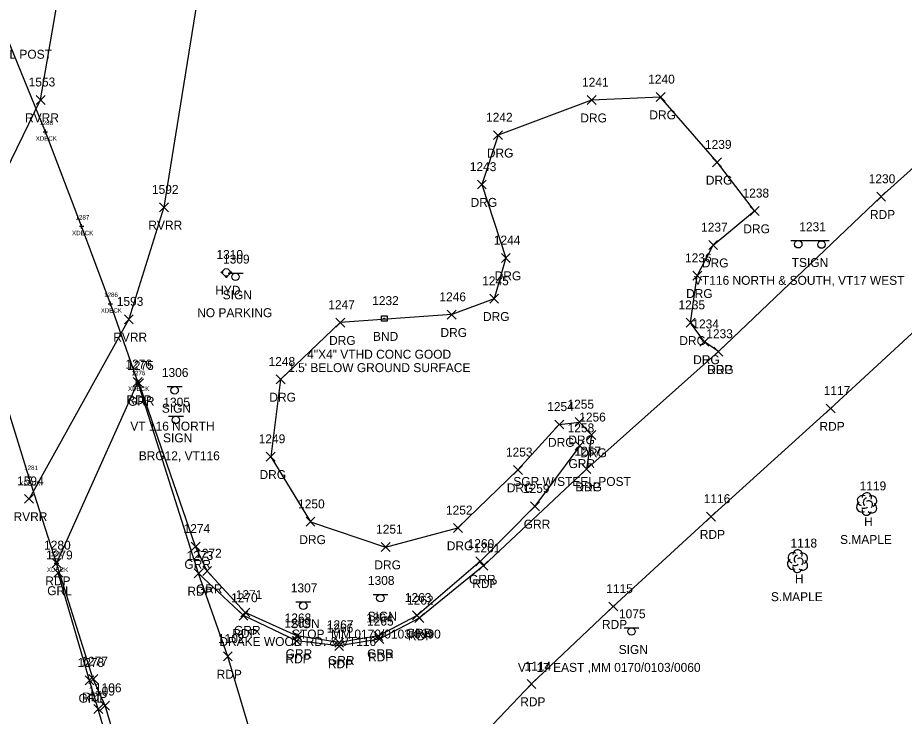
# Model space of a CAD drawing. Extents: x 1496556 to 1498241, y 599216 to 604470.
# Drawn here: x 1497204.8 to 1497403.3, y 603012.5 to 603168.8 of the extents above; entities that cross this region are included whole.
import ezdxf

# ---------------------------------------------------------------- set-up
doc = ezdxf.new("R2010")
doc.units = 0
for name, color, linetype in [('B_A', 7, 'Continuous'), ('B_I', 7, 'Continuous'), ('B_TIC', 7, 'Continuous'), ('BELB', 7, 'Continuous'), ('L_A', 7, 'Continuous'), ('L_C', 7, 'Continuous'), ('L_I', 7, 'Continuous'), ('L_TIC', 7, 'Continuous'), ('LAWE', 7, 'Continuous'), ('Level 18', 7, 'Continuous'), ('LTD', 7, 'Continuous'), ('M_A', 7, 'Continuous'), ('M_C', 7, 'Continuous'), ('M_I', 7, 'Continuous'), ('P_A', 7, 'Continuous'), ('P_I', 7, 'Continuous'), ('P_TIC', 7, 'Continuous'), ('PET', 7, 'Continuous'), ('R_A', 7, 'Continuous'), ('R_C', 7, 'Continuous'), ('R_I', 7, 'Continuous'), ('R_TIC', 7, 'Continuous'), ('RDG', 7, 'Continuous'), ('RGR', 7, 'Continuous'), ('S_A', 7, 'Continuous'), ('S_C', 7, 'Continuous'), ('S_I', 7, 'Continuous'), ('SSGN', 7, 'Continuous'), ('U_A', 7, 'Continuous'), ('U_I', 7, 'Continuous'), ('UWFH', 7, 'Continuous')]:
    doc.layers.add(name, color=color, linetype=linetype)

msp = doc.modelspace()

# ---------------------------------------------------------------- linework, layer by layer
at = {"layer": 'B_TIC'}
for p, q in [((1497211.03, 603143.32), (1497211.1, 603143.32)), ((1497219.15, 603122.16), (1497219.22, 603122.16)), ((1497225.58, 603104.83), (1497225.65, 603104.83)), ((1497231.71, 603087.32), (1497231.78, 603087.32)), ((1497207.36, 603066.11), (1497207.44, 603066.11)), ((1497213.54, 603046.79), (1497213.61, 603046.79))]:
    msp.add_line(p, q, dxfattribs=at)
for points in [[(1497211.03, 603142.82), (1497211.03, 603143.82)], [(1497210.53, 603143.32), (1497211.53, 603143.32)], [(1497218.64, 603122.16), (1497219.64, 603122.16)], [(1497219.14, 603121.66), (1497219.14, 603122.66)], [(1497225.08, 603104.83), (1497226.08, 603104.83)], [(1497225.58, 603104.33), (1497225.58, 603105.33)], [(1497231.2, 603087.32), (1497232.2, 603087.32)], [(1497231.7, 603086.82), (1497231.7, 603087.82)], [(1497207.36, 603065.61), (1497207.36, 603066.61)], [(1497206.86, 603066.11), (1497207.86, 603066.11)], [(1497213.03, 603046.79), (1497214.03, 603046.79)], [(1497213.53, 603046.29), (1497213.53, 603047.29)]]:
    msp.add_lwpolyline(points, dxfattribs=at)
at = {"layer": 'BELB'}
for points in [[(1497213.53, 603046.79), (1497207.36, 603066.11), (1497200.63, 603087.66), (1497189.92, 603115.25), (1497185.37, 603127.09), (1497183.49, 603131.83), (1497200.78, 603168.36)], [(1497231.7, 603087.32), (1497225.58, 603104.83), (1497219.14, 603122.16), (1497211.03, 603143.32), (1497200.78, 603168.36)]]:
    msp.add_lwpolyline(points, dxfattribs=at)
at = {"layer": 'L_TIC'}
for points in [[(1497208.98, 603149.46), (1497210.98, 603151.46)], [(1497210.98, 603149.46), (1497208.98, 603151.46)], [(1497236.58, 603125.42), (1497238.58, 603127.42)], [(1497238.58, 603125.42), (1497236.58, 603127.42)], [(1497228.71, 603100.35), (1497230.71, 603102.35)], [(1497230.71, 603100.35), (1497228.71, 603102.35)], [(1497206.4, 603060.16), (1497208.4, 603062.16)], [(1497208.4, 603060.16), (1497206.4, 603062.16)]]:
    msp.add_lwpolyline(points, dxfattribs=at)
at = {"layer": 'LAWE'}
for points in [[(1497189.81, 603091.49), (1497191.67, 603112.98), (1497209.98, 603150.46), (1497214.03, 603174.34), (1497209.01, 603206.37), (1497211.24, 603222.01), (1497227.45, 603268.03), (1497246.38, 603332.34), (1497269.89, 603360.04), (1497296.95, 603397.6), (1497313.57, 603422.44), (1497323.64, 603438.94), (1497334.8, 603445.38), (1497344.77, 603450.19), (1497370.1, 603467.8), (1497419.49, 603471.31), (1497456.04, 603468.84), (1497488.04, 603460.85), (1497518.38, 603461.84), (1497564.45, 603467.31)], [(1497257.29, 603233.96), (1497249.44, 603200.12), (1497237.58, 603126.42), (1497229.71, 603101.35), (1497207.4, 603061.16)]]:
    msp.add_lwpolyline(points, dxfattribs=at)
at = {"layer": 'Level 18'}
msp.add_lwpolyline([(1497286.25, 603102.14), (1497287.5, 603102.14), (1497287.5, 603100.89), (1497286.25, 603100.89)], close=True, dxfattribs=at)
msp.add_circle((1497286.87, 603101.52), 0.0833, dxfattribs=at)
at = {"layer": 'LTD'}
for p, q in [((1497394.85, 603060.05), (1497394.85, 603060.05)), ((1497394.85, 603060.05), (1497394.85, 603060.05)), ((1497379.36, 603047.25), (1497379.36, 603047.25)), ((1497379.36, 603047.25), (1497379.36, 603047.25))]:
    msp.add_line(p, q, dxfattribs=at)
for centre in [(1497394.89, 603061.48), (1497379.41, 603048.68)]:
    msp.add_arc(centre, 1.05, 335.5272, 180.9563, dxfattribs=at)
for centre, major_axis, ratio, start_param, end_param in [((1497394.05, 603060.72), (1.21, -0.51), 0.895232, 1.570796, 4.712389), ((1497394.64, 603060.51), (-0.208, -0.792), 0.645439, 3.141593, 6.283185), ((1497395.35, 603059.88), (-0.5, 0.667), 0.989748, 3.141593, 6.283185), ((1497395.89, 603060.63), (-1.14, -0.48), 0.949671, 1.570796, 4.712389), ((1497393.76, 603059.34), (0.58, -1.04), 0.959034, 3.141593, 6.283185), ((1497394.85, 603058.55), (0.26, 1.06), 0.942809, 1.570796, 4.712389), ((1497394.39, 603059.3), (-0.625, -0.083), 0.423636, 0, 3.141593), ((1497395.85, 603059.22), (-1.09, 0.79), 0.841452, 1.570796, 4.712389), ((1497378.57, 603047.91), (1.21, -0.51), 0.895232, 1.570796, 4.712389), ((1497379.16, 603047.71), (-0.208, -0.792), 0.645439, 3.141593, 6.283185), ((1497380.41, 603047.83), (-1.14, -0.48), 0.949671, 1.570796, 4.712389), ((1497378.28, 603046.54), (0.58, -1.04), 0.959034, 3.141593, 6.283185), ((1497379.86, 603047.08), (-0.5, 0.667), 0.989748, 3.141593, 6.283185), ((1497380.36, 603046.41), (-1.09, 0.79), 0.841452, 1.570796, 4.712389), ((1497379.36, 603045.75), (0.26, 1.06), 0.942809, 1.570796, 4.712389), ((1497378.91, 603046.5), (-0.625, -0.083), 0.423636, 0, 3.141593)]:
    msp.add_ellipse(centre, major_axis=major_axis, ratio=ratio, start_param=start_param, end_param=end_param, dxfattribs=at)
at = {"layer": 'P_TIC'}
for points in [[(1497397.1, 603127.8), (1497399.1, 603129.8)], [(1497399.1, 603127.8), (1497397.1, 603129.8)], [(1497360.66, 603093.11), (1497362.66, 603095.11)], [(1497362.66, 603093.11), (1497360.66, 603095.11)], [(1497230.7, 603086.32), (1497232.7, 603088.32)], [(1497232.7, 603086.32), (1497230.7, 603088.32)], [(1497385.8, 603080.38), (1497387.8, 603082.38)], [(1497387.8, 603080.38), (1497385.8, 603082.38)], [(1497331.15, 603066.83), (1497333.15, 603068.83)], [(1497333.15, 603066.83), (1497331.15, 603068.83)], [(1497359.02, 603056.19), (1497361.02, 603058.19)], [(1497361.02, 603056.19), (1497359.02, 603058.19)], [(1497212.53, 603045.79), (1497214.53, 603047.79)], [(1497214.53, 603045.79), (1497212.53, 603047.79)], [(1497212.53, 603045.79), (1497214.53, 603047.79)], [(1497214.53, 603045.79), (1497212.53, 603047.79)], [(1497308.09, 603045.17), (1497310.09, 603047.17)], [(1497310.09, 603045.17), (1497308.09, 603047.17)], [(1497244.34, 603043.47), (1497246.34, 603045.47)], [(1497246.34, 603043.47), (1497244.34, 603045.47)], [(1497244.34, 603043.47), (1497246.34, 603045.47)], [(1497246.34, 603043.47), (1497244.34, 603045.47)], [(1497337.13, 603036.05), (1497339.13, 603038.05)], [(1497339.13, 603036.05), (1497337.13, 603038.05)], [(1497254.38, 603034.01), (1497256.38, 603036.01)], [(1497256.38, 603034.01), (1497254.38, 603036.01)], [(1497293.72, 603033.46), (1497295.72, 603035.46)], [(1497295.72, 603033.46), (1497293.72, 603035.46)], [(1497284.78, 603028.77), (1497286.78, 603030.77)], [(1497286.78, 603028.77), (1497284.78, 603030.77)], [(1497266.28, 603028.35), (1497268.28, 603030.35)], [(1497268.28, 603028.35), (1497266.28, 603030.35)], [(1497275.79, 603027.23), (1497277.79, 603029.23)], [(1497277.79, 603027.23), (1497275.79, 603029.23)], [(1497250.88, 603024.88), (1497252.88, 603026.88)], [(1497252.88, 603024.88), (1497250.88, 603026.88)], [(1497220.77, 603019.8), (1497222.77, 603021.8)], [(1497222.77, 603019.8), (1497220.77, 603021.8)], [(1497318.84, 603018.72), (1497320.84, 603020.72)], [(1497320.84, 603018.72), (1497318.84, 603020.72)], [(1497223.39, 603013.86), (1497225.39, 603015.86)], [(1497225.39, 603013.86), (1497223.39, 603015.86)]]:
    msp.add_lwpolyline(points, dxfattribs=at)
at = {"layer": 'PET'}
for points in [[(1497580.33, 603293.36), (1497544.07, 603260.5), (1497503.96, 603223.83), (1497469.44, 603192.83), (1497432.27, 603159.48), (1497398.1, 603128.8), (1497361.66, 603094.11), (1497332.15, 603067.83), (1497309.09, 603046.17), (1497294.72, 603034.46), (1497285.78, 603029.77), (1497276.79, 603028.23), (1497267.28, 603029.35), (1497255.38, 603035.01), (1497245.34, 603044.47)], [(1497277.08, 602932.51), (1497278.76, 602955.27), (1497283.83, 602972.38), (1497292.85, 602989.5), (1497302.51, 603001.53), (1497319.84, 603019.72), (1497338.13, 603037.05), (1497360.02, 603057.19), (1497386.8, 603081.38), (1497411.61, 603104.29), (1497436.99, 603126.72), (1497459.34, 603147.15), (1497493.2, 603178.11), (1497522.29, 603204.31), (1497552.95, 603231.97)], [(1497283.12, 602906.81), (1497277.08, 602932.51), (1497269.71, 602963.41), (1497262.37, 602990.53), (1497251.88, 603025.88), (1497245.34, 603044.47), (1497231.7, 603087.32), (1497213.53, 603046.79)], [(1497255.35, 601840.33), (1497260.72, 601945.51), (1497260.6, 601945.5), (1497265.21, 602060.91), (1497267.76, 602124.12), (1497271.3, 602209.29), (1497274.95, 602307.82), (1497276.81, 602364.31), (1497278.84, 602406.87), (1497280.41, 602449.54), (1497282.45, 602505.14), (1497283.29, 602549.03), (1497283.31, 602599.78), (1497282.4, 602667.07), (1497280.87, 602701.36), (1497277.35, 602744.02), (1497266.99, 602833.93), (1497261.25, 602868.44), (1497249.2, 602924.4), (1497241.75, 602954.09), (1497234.18, 602981.9), (1497224.39, 603014.86), (1497221.77, 603020.8), (1497213.53, 603046.79)]]:
    msp.add_lwpolyline(points, dxfattribs=at)
at = {"layer": 'R_TIC'}
for points in [[(1497347.74, 603150.1), (1497349.74, 603152.1)], [(1497349.74, 603150.1), (1497347.74, 603152.1)], [(1497332.28, 603149.41), (1497334.28, 603151.41)], [(1497334.28, 603149.41), (1497332.28, 603151.41)], [(1497311.37, 603141.56), (1497313.37, 603143.56)], [(1497313.37, 603141.56), (1497311.37, 603143.56)], [(1497360.37, 603135.49), (1497362.37, 603137.49)], [(1497362.37, 603135.49), (1497360.37, 603137.49)], [(1497307.72, 603130.51), (1497309.72, 603132.51)], [(1497309.72, 603130.51), (1497307.72, 603132.51)], [(1497368.77, 603124.6), (1497370.77, 603126.6)], [(1497370.77, 603124.6), (1497368.77, 603126.6)], [(1497359.5, 603116.96), (1497361.5, 603118.96)], [(1497361.5, 603116.96), (1497359.5, 603118.96)], [(1497313.1, 603114.07), (1497315.1, 603116.07)], [(1497315.1, 603114.07), (1497313.1, 603116.07)], [(1497355.95, 603110.1), (1497357.95, 603112.1)], [(1497357.95, 603110.1), (1497355.95, 603112.1)], [(1497310.49, 603104.96), (1497312.49, 603106.96)], [(1497312.49, 603104.96), (1497310.49, 603106.96)], [(1497300.98, 603101.38), (1497302.98, 603103.38)], [(1497302.98, 603101.38), (1497300.98, 603103.38)], [(1497276.05, 603099.61), (1497278.05, 603101.61)], [(1497278.05, 603099.61), (1497276.05, 603101.61)], [(1497354.44, 603099.57), (1497356.44, 603101.57)], [(1497356.44, 603099.57), (1497354.44, 603101.57)], [(1497357.54, 603095.3), (1497359.54, 603097.3)], [(1497359.54, 603095.3), (1497357.54, 603097.3)], [(1497360.66, 603093.11), (1497362.66, 603095.11)], [(1497362.66, 603093.11), (1497360.66, 603095.11)], [(1497262.68, 603086.9), (1497264.68, 603088.9)], [(1497264.68, 603086.9), (1497262.68, 603088.9)], [(1497231.03, 603085.99), (1497233.03, 603087.99)], [(1497233.03, 603085.99), (1497231.03, 603087.99)], [(1497325.05, 603076.8), (1497327.05, 603078.8)], [(1497327.05, 603076.8), (1497325.05, 603078.8)], [(1497329.58, 603077.33), (1497331.58, 603079.33)], [(1497331.58, 603077.33), (1497329.58, 603079.33)], [(1497332.27, 603074.46), (1497334.27, 603076.46)], [(1497334.27, 603074.46), (1497332.27, 603076.46)], [(1497329.63, 603072.04), (1497331.63, 603074.04)], [(1497331.63, 603072.04), (1497329.63, 603074.04)], [(1497260.49, 603069.59), (1497262.49, 603071.59)], [(1497262.49, 603069.59), (1497260.49, 603071.59)], [(1497315.81, 603066.62), (1497317.81, 603068.62)], [(1497317.81, 603066.62), (1497315.81, 603068.62)], [(1497331.15, 603066.83), (1497333.15, 603068.83)], [(1497333.15, 603066.83), (1497331.15, 603068.83)], [(1497319.62, 603058.49), (1497321.62, 603060.49)], [(1497321.62, 603058.49), (1497319.62, 603060.49)], [(1497269.38, 603055.02), (1497271.38, 603057.02)], [(1497271.38, 603055.02), (1497269.38, 603057.02)], [(1497302.39, 603053.64), (1497304.39, 603055.64)], [(1497304.39, 603053.64), (1497302.39, 603055.64)], [(1497243.66, 603049.49), (1497245.66, 603051.49)], [(1497245.66, 603049.49), (1497243.66, 603051.49)], [(1497286.19, 603049.37), (1497288.19, 603051.37)], [(1497288.19, 603049.37), (1497286.19, 603051.37)], [(1497307.38, 603046.14), (1497309.38, 603048.14)], [(1497309.38, 603046.14), (1497307.38, 603048.14)], [(1497212.91, 603043.59), (1497214.91, 603045.59)], [(1497214.91, 603043.59), (1497212.91, 603045.59)], [(1497246.25, 603043.98), (1497248.25, 603045.98)], [(1497248.25, 603043.98), (1497246.25, 603045.98)], [(1497254.77, 603034.71), (1497256.77, 603036.71)], [(1497256.77, 603034.71), (1497254.77, 603036.71)], [(1497293.23, 603034.06), (1497295.23, 603036.06)], [(1497295.23, 603034.06), (1497293.23, 603036.06)], [(1497266.33, 603029.49), (1497268.33, 603031.49)], [(1497268.33, 603029.49), (1497266.33, 603031.49)], [(1497284.58, 603029.48), (1497286.58, 603031.48)], [(1497286.58, 603029.48), (1497284.58, 603031.48)], [(1497275.79, 603027.97), (1497277.79, 603029.97)], [(1497277.79, 603027.97), (1497275.79, 603029.97)], [(1497219.92, 603019.52), (1497221.92, 603021.52)], [(1497221.92, 603019.52), (1497219.92, 603021.52)], [(1497221.87, 603013.11), (1497223.87, 603015.11)], [(1497223.87, 603013.11), (1497221.87, 603015.11)]]:
    msp.add_lwpolyline(points, dxfattribs=at)
at = {"layer": 'RDG'}
msp.add_lwpolyline([(1497361.66, 603094.11), (1497358.54, 603096.3), (1497355.44, 603100.57), (1497356.95, 603111.1), (1497360.5, 603117.96), (1497369.77, 603125.6), (1497361.37, 603136.49), (1497348.74, 603151.1), (1497333.28, 603150.41), (1497312.37, 603142.56), (1497308.72, 603131.51), (1497314.1, 603115.07), (1497311.49, 603105.96), (1497301.98, 603102.38), (1497277.05, 603100.61), (1497263.68, 603087.9), (1497261.49, 603070.59), (1497270.38, 603056.02), (1497287.19, 603050.37), (1497303.39, 603054.64), (1497316.81, 603067.62), (1497326.05, 603077.8), (1497330.58, 603078.33), (1497333.27, 603075.46), (1497332.15, 603067.83)], dxfattribs=at)
at = {"layer": 'RGR'}
for points in [[(1497330.63, 603073.04), (1497320.62, 603059.49), (1497308.38, 603047.14), (1497294.23, 603035.06), (1497285.58, 603030.48), (1497276.79, 603028.97), (1497267.33, 603030.49), (1497255.77, 603035.71), (1497247.25, 603044.98), (1497244.66, 603050.49), (1497232.03, 603086.99)], [(1497237.35, 602946.59), (1497236.34, 602952.82), (1497233.63, 602971.81), (1497228.13, 602995.86), (1497222.87, 603014.11), (1497220.92, 603020.52), (1497213.91, 603044.59)]]:
    msp.add_lwpolyline(points, dxfattribs=at)
at = {"layer": 'SSGN'}
for p, q in [((1497377.89, 603118.98), (1497386.48, 603118.98)), ((1497381.91, 603118.07), (1497381.91, 603118.07)), ((1497251.95, 603111.68), (1497255.28, 603111.68)), ((1497253.6, 603110.84), (1497253.6, 603110.84)), ((1497238.31, 603086.28), (1497241.64, 603086.28)), ((1497239.96, 603085.45), (1497239.96, 603085.45)), ((1497238.59, 603079.66), (1497241.92, 603079.66)), ((1497240.24, 603078.82), (1497240.24, 603078.82)), ((1497284.38, 603039.75), (1497287.71, 603039.75)), ((1497286.02, 603038.91), (1497286.02, 603038.91)), ((1497267.11, 603038.07), (1497270.45, 603038.07)), ((1497268.76, 603037.23), (1497268.76, 603037.23)), ((1497340.56, 603032.28), (1497343.9, 603032.28)), ((1497342.21, 603031.45), (1497342.21, 603031.45))]:
    msp.add_line(p, q, dxfattribs=at)
for centre in [(1497379.55, 603118.14), (1497384.76, 603118.07), (1497253.6, 603110.84), (1497239.96, 603085.45), (1497240.24, 603078.82), (1497286.02, 603038.91), (1497268.76, 603037.23), (1497342.21, 603031.45)]:
    msp.add_circle(centre, 0.833, dxfattribs=at)
at = {"layer": 'UWFH'}
msp.add_line((1497251.54, 603111.85), (1497251.54, 603111.85), dxfattribs=at)
for centre, radius in [((1497251.54, 603111.85), 0.833), ((1497250.54, 603111.85), 0.167), ((1497251.54, 603110.85), 0.167), ((1497252.54, 603111.85), 0.167)]:
    msp.add_circle(centre, radius, dxfattribs=at)

# ---------------------------------------------------------------- texts
at = {"layer": 'B_A'}
for p in [(1497208.87, 603141.32), (1497216.99, 603120.16), (1497223.42, 603102.83), (1497229.54, 603085.32), (1497205.2, 603064.11), (1497211.38, 603044.79)]:
    msp.add_text('XDECK', height=1, dxfattribs=at).set_placement(p)
at = {"layer": 'B_I'}
for s, p in [('1288', (1497209.68, 603144.82)), ('1287', (1497217.8, 603123.66)), ('1286', (1497224.2, 603106.33)), ('1276', (1497230.33, 603088.82)), ('1281', (1497206.3, 603067.61)), ('1280', (1497212.14, 603048.29))]:
    msp.add_text(s, height=1, dxfattribs=at).set_placement(p)
at = {"layer": 'L_A'}
for s, p in [('RVRR', (1497206.49, 603145.46)), ('RVRR', (1497234.09, 603121.42)), ('RVRR', (1497226.23, 603096.35)), ('RVRR', (1497203.92, 603056.16)), ('H', (1497394.28, 603055.05)), ('H', (1497378.8, 603042.25))]:
    msp.add_text(s, height=2, dxfattribs=at).set_placement(p)
at = {"layer": 'L_C'}
for p in [(1497388.91, 603051.05), (1497373.43, 603038.25)]:
    msp.add_text('S.MAPLE', height=2, dxfattribs=at).set_placement(p)
at = {"layer": 'L_I'}
for s, p in [('1553', (1497207.29, 603153.46)), ('1592', (1497234.89, 603129.42)), ('1593', (1497227.02, 603104.35)), ('1594', (1497204.71, 603064.16)), ('1119', (1497393.28, 603063.05)), ('1118', (1497377.81, 603050.25))]:
    msp.add_text(s, height=2, dxfattribs=at).set_placement(p)
at = {"layer": 'M_A'}
msp.add_text('BND', height=2, dxfattribs=at).set_placement((1497284.36, 603096.52))
at = {"layer": 'M_C'}
for s, p in [('4"X4" VTHD CONC GOOD', (1497269.64, 603092.52)), ("1.5' BELOW GROUND SURFACE", (1497265.38, 603089.52))]:
    msp.add_text(s, height=2, dxfattribs=at).set_placement(p)
at = {"layer": 'M_I'}
msp.add_text('1232', height=2, dxfattribs=at).set_placement((1497284.18, 603104.52))
at = {"layer": 'P_A'}
for p in [(1497395.59, 603123.8), (1497359.15, 603089.11), (1497229.19, 603082.32), (1497384.29, 603076.38), (1497329.64, 603062.83), (1497357.51, 603052.19), (1497211.02, 603041.79), (1497211.02, 603041.79), (1497306.58, 603041.17), (1497242.83, 603039.47), (1497242.83, 603039.47), (1497335.61, 603032.05), (1497252.87, 603030.01), (1497292.21, 603029.46), (1497283.27, 603024.77), (1497264.77, 603024.35), (1497274.27, 603023.23), (1497249.37, 603020.88), (1497219.25, 603015.8), (1497317.32, 603014.72)]:
    msp.add_text('RDP', height=2, dxfattribs=at).set_placement(p)
at = {"layer": 'P_I'}
for s, p in [('1230', (1497395.32, 603131.8)), ('1233', (1497358.96, 603097.11)), ('1276', (1497228.95, 603090.32)), ('1117', (1497385.24, 603084.38)), ('1257', (1497329.46, 603070.83)), ('1116', (1497358.4, 603060.19)), ('1280', (1497210.75, 603049.79)), ('1280', (1497210.75, 603049.79)), ('1261', (1497306.91, 603049.17)), ('1273', (1497242.65, 603047.47)), ('1273', (1497242.65, 603047.47)), ('1115', (1497336.57, 603040.05)), ('1270', (1497252.61, 603038.01)), ('1262', (1497291.98, 603037.46)), ('1265', (1497283.04, 603032.77)), ('1269', (1497264.53, 603032.35)), ('1266', (1497273.99, 603031.23)), ('1102', (1497249.67, 603028.88)), ('1277', (1497219.07, 603023.8)), ('1114', (1497318.28, 603022.72)), ('1106', (1497222.13, 603017.86))]:
    msp.add_text(s, height=2, dxfattribs=at).set_placement(p)
at = {"layer": 'R_A'}
for s, p in [('DRG', (1497346.23, 603146.1)), ('DRG', (1497330.77, 603145.41)), ('DRG', (1497309.85, 603137.56)), ('DRG', (1497358.86, 603131.49)), ('DRG', (1497306.21, 603126.51)), ('DRG', (1497367.25, 603120.6)), ('DRG', (1497357.98, 603112.96)), ('DRG', (1497311.59, 603110.07)), ('DRG', (1497354.44, 603106.1)), ('DRG', (1497308.98, 603100.96)), ('DRG', (1497299.47, 603097.38)), ('DRG', (1497274.54, 603095.61)), ('DRG', (1497352.93, 603095.57)), ('DRG', (1497356.03, 603091.3)), ('DRG', (1497359.15, 603089.11)), ('DRG', (1497261.17, 603082.9)), ('GRR', (1497229.52, 603081.99)), ('DRG', (1497323.54, 603072.8)), ('DRG', (1497328.07, 603073.33)), ('DRG', (1497330.76, 603070.46)), ('GRR', (1497328.12, 603068.04)), ('DRG', (1497258.97, 603065.59)), ('DRG', (1497314.3, 603062.62)), ('DRG', (1497329.64, 603062.83)), ('GRR', (1497318.11, 603054.49)), ('DRG', (1497267.87, 603051.02)), ('DRG', (1497300.88, 603049.64)), ('GRR', (1497242.15, 603045.49)), ('DRG', (1497284.68, 603045.37)), ('GRR', (1497305.87, 603042.14)), ('GRL', (1497211.45, 603039.59)), ('GRR', (1497244.74, 603039.98)), ('GRR', (1497253.26, 603030.71)), ('GRR', (1497291.72, 603030.06)), ('GRR', (1497264.82, 603025.49)), ('GRR', (1497283.06, 603025.48)), ('GRR', (1497274.28, 603023.97)), ('GRL', (1497218.46, 603015.52))]:
    msp.add_text(s, height=2, dxfattribs=at).set_placement(p)
at = {"layer": 'R_C'}
for p in [(1497186.2, 603159.67), (1497315.77, 603064.04)]:
    msp.add_text('SGR W/STEEL POST', height=2, dxfattribs=at).set_placement(p)
at = {"layer": 'R_I'}
for s, p in [('1240', (1497345.96, 603154.1)), ('1241', (1497331.16, 603153.41)), ('1242', (1497309.67, 603145.56)), ('1239', (1497358.67, 603139.49)), ('1243', (1497306.03, 603134.51)), ('1238', (1497367.07, 603128.6)), ('1237', (1497357.8, 603120.96)), ('1244', (1497311.41, 603118.07)), ('1236', (1497354.21, 603114.1)), ('1245', (1497308.8, 603108.96)), ('1246', (1497299.23, 603105.38)), ('1247', (1497274.36, 603103.61)), ('1235', (1497352.74, 603103.57)), ('1234', (1497355.85, 603099.3)), ('1233', (1497358.96, 603097.11)), ('1248', (1497260.99, 603090.9)), ('1275', (1497229.34, 603089.99)), ('1254', (1497323.36, 603080.8)), ('1255', (1497327.89, 603081.33)), ('1256', (1497330.52, 603078.46)), ('1258', (1497327.94, 603076.04)), ('1249', (1497258.79, 603073.59)), ('1253', (1497314.12, 603070.62)), ('1257', (1497329.46, 603070.83)), ('1259', (1497317.92, 603062.49)), ('1250', (1497267.6, 603059.02)), ('1252', (1497300.7, 603057.64)), ('1274', (1497241.97, 603053.49)), ('1251', (1497285.06, 603053.37)), ('1260', (1497305.55, 603050.14)), ('1279', (1497211.21, 603047.59)), ('1272', (1497244.56, 603047.98)), ('1271', (1497253.65, 603038.71)), ('1263', (1497291.49, 603038.06)), ('1268', (1497264.59, 603033.49)), ('1264', (1497282.83, 603033.48)), ('1267', (1497274.05, 603031.97)), ('1278', (1497218.23, 603023.52)), ('1109', (1497220.66, 603017.11))]:
    msp.add_text(s, height=2, dxfattribs=at).set_placement(p)
at = {"layer": 'S_A'}
for s, p in [('TSIGN', (1497378.08, 603113.06)), ('SIGN', (1497250.73, 603105.82)), ('SIGN', (1497237.1, 603080.43)), ('SIGN', (1497237.38, 603073.8)), ('SIGN', (1497283.16, 603033.89)), ('SIGN', (1497265.9, 603032.21)), ('SIGN', (1497339.35, 603026.43))]:
    msp.add_text(s, height=2, dxfattribs=at).set_placement(p)
at = {"layer": 'S_C'}
for s, p in [('VT116 NORTH & SOUTH, VT17 WEST', (1497356.21, 603109.06)), ('NO PARKING', (1497245.02, 603101.82)), ('VT 116 NORTH', (1497230.05, 603076.43)), ('BRG12, VT116', (1497231.94, 603069.8)), ('STOP, MM 0170/0103/0990', (1497266.23, 603029.89)), ('DRAKE WOOD RD. & VT116', (1497249.99, 603028.21)), ('VT 17 EAST ,MM 0170/0103/0060', (1497316.8, 603022.43))]:
    msp.add_text(s, height=2, dxfattribs=at).set_placement(p)
at = {"layer": 'S_I'}
for s, p in [('1231', (1497379.78, 603121.06)), ('1309', (1497250.8, 603113.82)), ('1306', (1497237.11, 603088.43)), ('1305', (1497237.45, 603081.8)), ('1308', (1497283.23, 603041.89)), ('1307', (1497265.97, 603040.21)), ('1075', (1497339.42, 603034.43))]:
    msp.add_text(s, height=2, dxfattribs=at).set_placement(p)
at = {"layer": 'U_A'}
msp.add_text('HYD', height=2, dxfattribs=at).set_placement((1497249.06, 603106.85))
at = {"layer": 'U_I'}
msp.add_text('1310', height=2, dxfattribs=at).set_placement((1497249.33, 603114.85))

doc.saveas('drawing.dxf')
